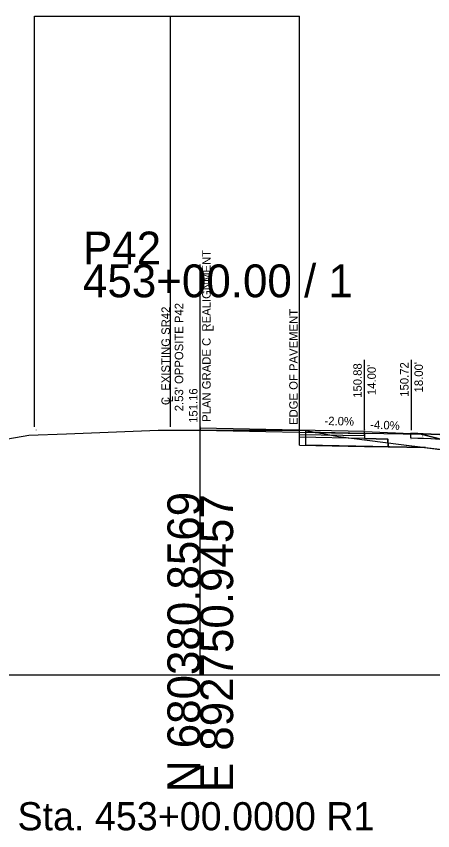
# Model space of a CAD drawing. Extents: x -26 to 4303, y -13 to 10775.
# Drawn here: x 134.3 to 169.8, y 1486.7 to 1556.2 of the extents above; entities that cross this region are included whole.
import ezdxf

# ---------------------------------------------------------------- set-up
doc = ezdxf.new("R2010")
doc.units = 0
for name, color, linetype in [('_CIVIL_CONSTRUCTION', 7, 'Continuous'), ('ASHPALT_12_5MM1', 7, 'Continuous'), ('Default', 7, 'Continuous'), ('Draft_XS_Text', 7, 'Continuous'), ('DTM_P_FINISHED_GRADE', 7, 'Continuous'), ('DTM_X_GROUND', 7, 'Continuous'), ('X_ROW', 7, 'Continuous'), ('X_TRANS_EOP', 7, 'Continuous'), ('XS_CELL', 7, 'Continuous'), ('XS_M_EXCAVATION_LIMITS', 7, 'Continuous'), ('XS_P_DR_GRAVEL', 7, 'Continuous'), ('XS_P_GROUND', 7, 'Continuous'), ('XS_P_SUBGRADE_GRANULAR', 7, 'Continuous'), ('XS_P_TX_CLEARZONE', 7, 'Continuous'), ('XS_P_TX_FS_BS', 7, 'Continuous'), ('XS_SHEET_EW_TX_AREA', 7, 'Continuous')]:
    doc.layers.add(name, color=color, linetype=linetype)

msp = doc.modelspace()

# ---------------------------------------------------------------- linework, layer by layer
msp.add_line((164, 1520.4), (164, 1520.15))
msp.add_lwpolyline([(158.46, 1520.511), (164, 1520.4), (164, 1520.587), (164, 1520.587), (158.985, 1520.688)])
at = {"layer": 'ASHPALT_12_5MM1'}
msp.add_line((164, 1520.754), (150, 1521.034), dxfattribs=at)
at = {"layer": 'Default'}
msp.add_lwpolyline([(150, 1521.034), (150, 1521.034), (150, 1521.034), (150, 1520.867), (150, 1520.867), (164, 1520.587), (164, 1520.754), (164, 1520.754), (150, 1521.034)], dxfattribs=at)
at = {"layer": 'DTM_P_FINISHED_GRADE'}
for p, q in [((167.906, 1520.598), (167.907, 1520.598)), ((167.907, 1520.598), (168, 1520.594)), ((168, 1520.594), (168.543, 1520.572)), ((168.543, 1520.572), (168.551, 1520.572)), ((168.551, 1520.572), (169.006, 1520.553)), ((169.006, 1520.553), (169.654, 1520.52)), ((169.654, 1520.52), (169.666, 1520.52)), ((169.666, 1520.52), (170.422, 1520.488))]:
    msp.add_line(p, q, dxfattribs=at)
at = {"layer": 'DTM_X_GROUND'}
msp.add_lwpolyline([(132.267, 1519.899), (135.382, 1520.433), (138.594, 1520.546), (146.412, 1520.868), (147.073, 1520.864), (150.015, 1520.869), (150.039, 1520.869), (158.801, 1520.858), (159.17, 1520.825), (160.722, 1520.52), (161.768, 1520.323), (172.007, 1519.023), (172.659, 1518.99), (175.189, 1518.664), (179.846, 1518.137), (193.83, 1516.708), (197.437, 1516.386), (203.804, 1515.876), (209.501, 1515.398), (209.508, 1515.398), (214.069, 1515.192), (233.709, 1514.282)], dxfattribs=at)
at = {"layer": 'X_ROW'}
for p, q in [((164, 1520.879), (164, 1520.879)), ((164, 1520.879), (164, 1520.879)), ((164, 1520.587), (164, 1520.754)), ((164, 1520.754), (168.595, 1520.57)), ((168.925, 1520.488), (164, 1520.587)), ((164, 1520.587), (164, 1520.587))]:
    msp.add_line(p, q, dxfattribs=at)
for points in [[(164, 1519.483), (166, 1519.443), (165.995, 1520.109), (165.995, 1520.109), (164, 1520.15), (164, 1520.15), (158.46, 1520.261)], [(158.46, 1519.594), (164, 1519.483), (164, 1519.483)]]:
    msp.add_lwpolyline(points, dxfattribs=at)
at = {"layer": 'X_TRANS_EOP'}
for p, q in [((135.857, 1521.159), (135.857, 1556.159)), ((135.857, 1556.159), (158.46, 1556.159)), ((147.47, 1521.159), (147.47, 1556.159)), ((158.46, 1521.159), (158.46, 1556.159))]:
    msp.add_line(p, q, dxfattribs=at)
at = {"layer": 'XS_CELL'}
for p, q in [((150, 1500), (150, 1535)), ((0, 1500), (150, 1500)), ((150, 1500), (300, 1500))]:
    msp.add_line(p, q, dxfattribs=at)
at = {"layer": 'XS_M_EXCAVATION_LIMITS'}
msp.add_line((158.46, 1519.594), (158.46, 1528.546), dxfattribs=at)
at = {"layer": 'XS_P_DR_GRAVEL'}
for p, q in [((167.906, 1520.598), (167.906, 1520.223)), ((167.907, 1520.598), (167.906, 1520.598)), ((167.906, 1520.223), (168.005, 1520.219)), ((168, 1520.594), (167.907, 1520.598)), ((168.543, 1520.572), (168, 1520.594)), ((168, 1520.594), (168, 1520.594)), ((168.005, 1520.219), (168.548, 1520.197)), ((168.551, 1520.572), (168.543, 1520.572)), ((168.548, 1520.197), (168.556, 1520.197)), ((169.006, 1520.553), (168.551, 1520.572)), ((168.556, 1520.197), (169.011, 1520.178)), ((169.654, 1520.52), (169.006, 1520.553)), ((169.012, 1520.178), (169.661, 1520.145)), ((169.666, 1520.52), (169.654, 1520.52)), ((169.659, 1520.145), (169.671, 1520.145)), ((170.422, 1520.488), (169.666, 1520.52)), ((169.671, 1520.145), (170.427, 1520.113)), ((167.906, 1520.098), (167.907, 1520.098)), ((168, 1520.094), (168, 1520.094))]:
    msp.add_line(p, q, dxfattribs=at)
at = {"layer": 'XS_P_GROUND'}
msp.add_lwpolyline([(192.386, 1513.59), (192.386, 1513.59), (180, 1517.719), (168.595, 1520.57)], dxfattribs=at)
at = {"layer": 'XS_P_SUBGRADE_GRANULAR'}
msp.add_lwpolyline([(169.199, 1519.379), (166, 1519.443), (166, 1519.443), (164, 1519.483), (164, 1519.483)], dxfattribs=at)
at = {"layer": 'XS_P_TX_CLEARZONE'}
for p, q in [((147.47, 1521.159), (147.47, 1527.159)), ((150, 1521.159), (150, 1527.159)), ((150, 1521.159), (150, 1527.159)), ((150, 1521.159), (150, 1527.159)), ((164, 1520.879), (164, 1526.879)), ((164, 1520.879), (164, 1526.879)), ((164, 1520.879), (164, 1526.879)), ((168, 1520.879), (168, 1526.879))]:
    msp.add_line(p, q, dxfattribs=at)
at = {"layer": 'XS_SHEET_EW_TX_AREA'}
for points in [[(168.96, 1519.382), (158.985, 1519.583), (158.985, 1520.841), (159.17, 1520.825), (159.946, 1520.672), (160.722, 1520.52), (161.768, 1520.323), (166.887, 1519.673), (169.2, 1519.378)], [(164, 1520.587), (164, 1520.15), (165.995, 1520.109), (166, 1519.443), (169.2, 1519.378), (177.059, 1518.453), (172.687, 1519.547), (168.925, 1520.488)]]:
    msp.add_lwpolyline(points, close=True, dxfattribs=at)

# ---------------------------------------------------------------- texts
at = {"layer": '_CIVIL_CONSTRUCTION'}
for height, p in [(0.001, (147.47, 1542.229)), (0.12, (135.961, 1520.819)), (0.12, (149.961, 1521.099)), (0.12, (163.961, 1520.819)), (0.12, (165.955, 1520.049)), (0.12, (168.886, 1520.303)), (0.12, (168.886, 1520.428)), (0.12, (165.955, 1519.925))]:
    msp.add_text('X', height=height, dxfattribs=at).set_placement(p)
at = {"layer": 'Draft_XS_Text'}
msp.add_text('Sta. 453+00.0000 R1', height=2.4, dxfattribs=at).set_placement((134.42, 1486.75))
at = {"layer": 'XS_CELL'}
for s, p in [('P42', (140, 1535)), ('453+00.00 / 1', (140, 1532.2))]:
    msp.add_text(s, height=2.8, dxfattribs=at).set_placement(p)
for s, p in [('N 680380.8569', (150, 1490)), ('E 892750.9457', (152.8, 1490))]:
    msp.add_text(s, height=2.8, rotation=90, dxfattribs=at).set_placement(p)
at = {"layer": 'XS_P_TX_CLEARZONE'}
for s, p in [('PLAN GRADE C  REALIGNMENT', (150.884, 1521.576)), ('C  EXISTING SR42', (147.412, 1523.004)), ("2.53' OPPOSITE P42", (148.542, 1522.484)), ('EDGE OF PAVEMENT', (158.302, 1521.312)), ('L', (151.134, 1529.286)), ('150.88', (163.76, 1523.626)), ('150.88', (163.76, 1523.626)), ('150.88', (163.76, 1523.626)), ("14.00'", (164.96, 1523.864)), ("14.00'", (164.96, 1523.864)), ("14.00'", (164.96, 1523.864)), ('150.72', (167.75, 1523.717)), ("18.00'", (168.974, 1524.09)), ('151.16', (149.76, 1521.49)), ('151.16', (149.76, 1521.49)), ('151.16', (149.76, 1521.49)), ('L', (147.661, 1523.255))]:
    msp.add_text(s, height=0.72, rotation=90, dxfattribs=at).set_placement(p)
at = {"layer": 'XS_P_TX_FS_BS'}
for s, rotation, p in [('-2.0%', 358.85424, (160.579, 1521.308)), ('-4.0%', 357.46748, (164.469, 1521.001))]:
    msp.add_text(s, height=0.72, rotation=rotation, dxfattribs=at).set_placement(p)

doc.saveas('drawing.dxf')
